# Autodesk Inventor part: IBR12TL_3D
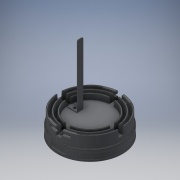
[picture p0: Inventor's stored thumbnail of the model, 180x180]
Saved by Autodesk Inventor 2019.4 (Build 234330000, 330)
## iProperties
Created: 2020-04
Part Number: IBR12TL_3D
Material: Generic
Document SubType Name: Modeling
Designer: EC
Density: 1 g/cm^3
Appearance: Default
Author: EC
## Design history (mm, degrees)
derived "IGBR12TL-XX-V.iam"
node "Solid26__test.ipt:1"
body "Srf1"
node "P110008_01-Piastrino UL LBXS RING 12x.ipt:1"
node "Spacer for Blade R UL.ipt:1"
node "PA90.ipt:1"
node "Solid21_1_test.ipt:1"
node "IGBR12TL-XX-V.iam_Bodies"
